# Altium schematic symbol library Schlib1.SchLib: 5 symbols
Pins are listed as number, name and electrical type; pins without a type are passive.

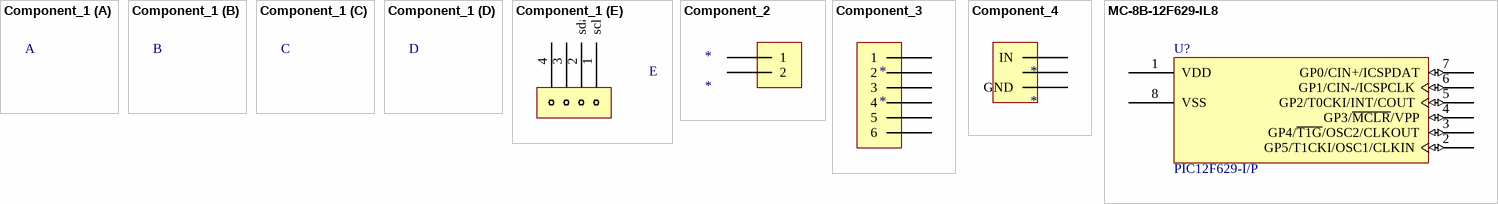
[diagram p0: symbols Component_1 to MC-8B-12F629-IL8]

## Component_1
designator ?
part E pins: 1 scl, 2 sda, 3 1, 4 0

## Component_2
designator *
pins: 6 2, ?1 1

## Component_3
designator *
pins: 7 1, 8 2, 9 3, 10 4, 11 5, 12 6

## Component_4
designator *
pins: 13 IN, 14, 15 GND

## MC-8B-12F629-IL8
designator U?, comment PIC12F629-I/P
FLASH-Based 8-Bit CMOS Microcontroller, 8-Pin PDIP, Industrial Temperature; Note1: Refer to data sheet (DS41190F) for details of supply voltage range under different conditions.
footprint PDIP300-P8 (DIP, 8-Leads, Row Spacing 7.62mm, Pitch 2.54mm, Body 9.5x6.6mm)
pins: 1 VDD (power), 2 GP5/T1CKI/OSC1/CLKIN (io), 3 GP4/~{T1G}/OSC2/CLKOUT (io), 4 GP3/~{MCLR}/VPP (io), 5 GP2/T0CKI/INT/COUT (io), 6 GP1/CIN-/ICSPCLK (io), 7 GP0/CIN+/ICSPDAT (io), 8 VSS (power)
